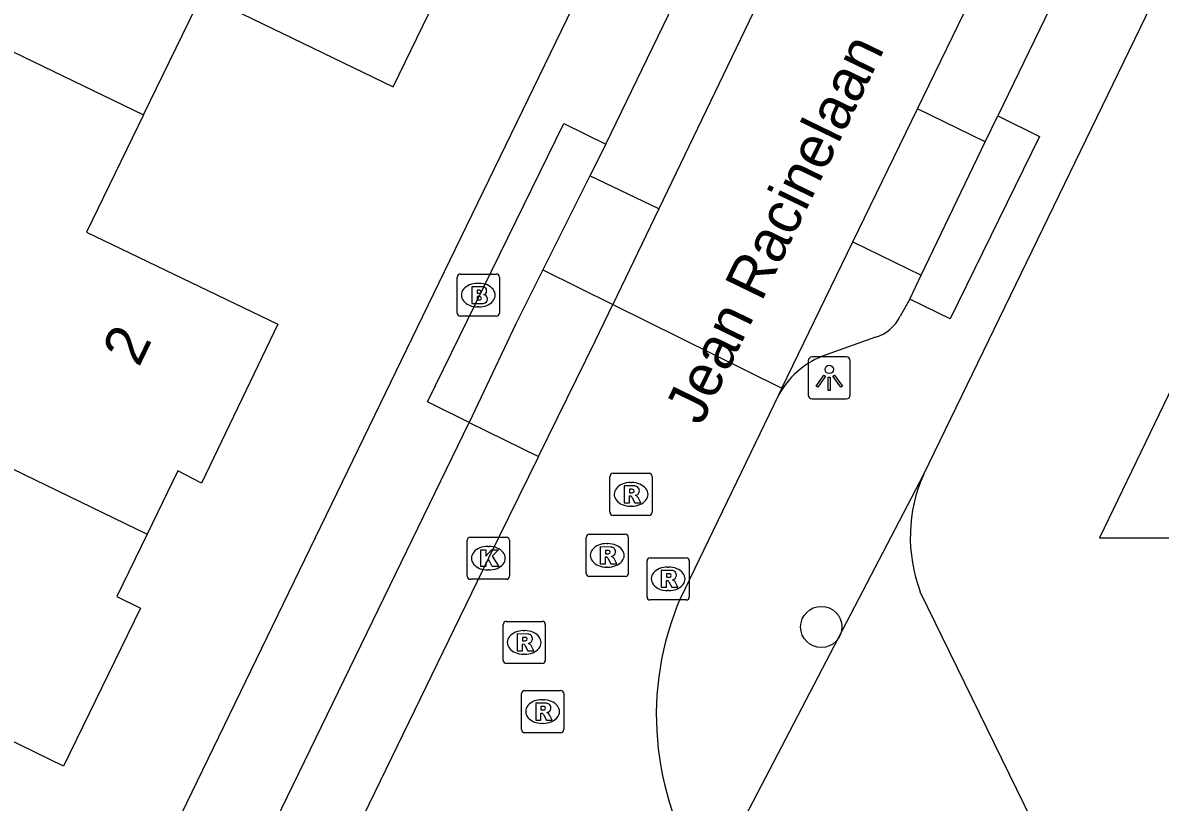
# Model space of a CAD drawing. Extents: x 160457 to 162082, y 388340 to 389736.
# Drawn here: x 160681.02 to 160707.98, y 388938.55 to 388957.02 of the extents above; entities that cross this region are included whole.
import ezdxf

# ---------------------------------------------------------------- set-up
doc = ezdxf.new("R2010")
doc.units = 0
for name, color, linetype in [('IMGEO_Boom', 7, 'Continuous'), ('IMGEO_Brandkraan', 7, 'Continuous'), ('IMGEO_Kolk', 7, 'Continuous'), ('IMGEO_Lichtpunt', 7, 'Continuous'), ('IMGEO_Openbare_ruimte_label', 7, 'Continuous'), ('IMGEO_Pand', 7, 'Continuous'), ('IMGEO_Pand_nummerreeks', 7, 'Continuous'), ('IMGEO_Parkeervlak_open', 7, 'Continuous'), ('IMGEO_Rijbaan_lokaal_gesloten', 7, 'Continuous'), ('IMGEO_Rijbaan_lokaal_open', 7, 'Continuous'), ('IMGEO_Rioolput', 7, 'Continuous'), ('IMGEO_Voetpad_open', 7, 'Continuous')]:
    doc.layers.add(name, color=color, linetype=linetype)

msp = doc.modelspace()

# ---------------------------------------------------------------- linework, layer by layer
at = {"layer": 'IMGEO_Boom'}
msp.add_circle((160699.949, 388942.7), 0.489, dxfattribs=at)
at = {"layer": 'IMGEO_Brandkraan'}
for p, q in [((160691.319, 388950.14), (160691.319, 388950.992)), ((160691.394, 388951.066), (160692.246, 388951.066)), ((160692.32, 388950.992), (160692.32, 388950.14)), ((160691.807, 388950.846), (160691.832, 388950.846)), ((160691.83, 388950.286), (160691.805, 388950.286)), ((160692.246, 388950.066), (160691.394, 388950.066))]:
    msp.add_line(p, q, dxfattribs=at)
for points in [[(160691.319, 388950.14), (160691.319, 388950.992)], [(160691.394, 388951.066), (160692.246, 388951.066)], [(160692.32, 388950.992), (160692.32, 388950.14)], [(160691.667, 388950.766), (160691.667, 388950.366), (160691.88, 388950.366)], [(160691.898, 388950.766), (160691.667, 388950.766)], [(160691.846, 388950.685), (160691.792, 388950.685), (160691.792, 388950.609)], [(160691.792, 388950.609), (160691.845, 388950.609)], [(160691.854, 388950.533), (160691.792, 388950.533), (160691.792, 388950.452)], [(160691.792, 388950.452), (160691.854, 388950.452)], [(160692.246, 388950.066), (160691.394, 388950.066)]]:
    msp.add_lwpolyline(points, dxfattribs=at)
for centre, radius, start, end in [((160691.396, 388950.99), 0.0765, 91.552, 178.448), ((160691.396, 388950.99), 0.0765, 91.552, 178.448), ((160692.244, 388950.99), 0.0765, 1.552, 88.448), ((160692.244, 388950.99), 0.0765, 1.552, 88.448), ((160691.847, 388950.647), 0.0379, 267.8285, 90.9355), ((160691.902, 388950.621), 0.145, 59.4692, 91.5367), ((160691.927, 388950.668), 0.0922, 285.5137, 58.1501), ((160691.855, 388950.492), 0.0404, 269.8759, 90.5077), ((160691.886, 388950.617), 0.251, 268.6676, 293.5347), ((160691.932, 388950.476), 0.105, 301.3115, 78.989), ((160691.396, 388950.142), 0.0765, 181.552, 268.448), ((160691.396, 388950.142), 0.0765, 181.552, 268.448), ((160692.244, 388950.142), 0.0765, 271.552, 358.448), ((160692.244, 388950.142), 0.0765, 271.552, 358.448)]:
    msp.add_arc(centre, radius, start, end, dxfattribs=at)
for centre, major_axis, ratio, start_param, end_param in [((160691.806, 388950.566), (-0.387, 0.002), 0.722429, 4.712389, 7.853982), ((160691.831, 388950.566), (-0.39, 0.002), 0.717154, 1.570796, 4.712389)]:
    msp.add_ellipse(centre, major_axis=major_axis, ratio=ratio, start_param=start_param, end_param=end_param, dxfattribs=at)
at = {"layer": 'IMGEO_Kolk'}
for p, q in [((160691.558, 388943.905), (160691.558, 388944.757)), ((160691.633, 388944.831), (160692.485, 388944.831)), ((160692.559, 388944.757), (160692.559, 388943.905)), ((160692.046, 388944.611), (160692.071, 388944.611)), ((160692.069, 388944.051), (160692.044, 388944.051)), ((160692.485, 388943.831), (160691.633, 388943.831))]:
    msp.add_line(p, q, dxfattribs=at)
for points in [[(160691.558, 388943.905), (160691.558, 388944.757)], [(160691.633, 388944.831), (160692.485, 388944.831)], [(160692.559, 388944.757), (160692.559, 388943.905)], [(160691.879, 388944.531), (160692.002, 388944.531), (160692.002, 388944.38), (160692.132, 388944.531), (160692.296, 388944.531), (160692.15, 388944.38), (160692.303, 388944.131), (160692.151, 388944.131), (160692.066, 388944.295), (160692.002, 388944.228), (160692.002, 388944.131), (160691.879, 388944.131), (160691.879, 388944.531)], [(160692.485, 388943.831), (160691.633, 388943.831)]]:
    msp.add_lwpolyline(points, dxfattribs=at)
for centre, start, end in [((160691.635, 388944.755), 91.552, 178.448), ((160691.635, 388944.755), 91.552, 178.448), ((160692.483, 388944.755), 1.552, 88.448), ((160692.483, 388944.755), 1.552, 88.448), ((160691.635, 388943.907), 181.552, 268.448), ((160691.635, 388943.907), 181.552, 268.448), ((160692.483, 388943.907), 271.552, 358.448), ((160692.483, 388943.907), 271.552, 358.448)]:
    msp.add_arc(centre, 0.0765, start, end, dxfattribs=at)
for centre, major_axis, ratio, start_param, end_param in [((160692.045, 388944.331), (-0.387, 0.002), 0.722429, 4.712389, 7.853982), ((160692.07, 388944.331), (-0.39, 0.002), 0.717154, 1.570796, 4.712389)]:
    msp.add_ellipse(centre, major_axis=major_axis, ratio=ratio, start_param=start_param, end_param=end_param, dxfattribs=at)
at = {"layer": 'IMGEO_Lichtpunt'}
for p, q in [((160700.541, 388949.103), (160699.733, 388949.103)), ((160700.541, 388949.103), (160699.733, 388949.103)), ((160699.639, 388949.008), (160699.639, 388948.201)), ((160699.639, 388949.008), (160699.639, 388948.201)), ((160700.635, 388948.201), (160700.635, 388949.008)), ((160700.635, 388948.201), (160700.635, 388949.008)), ((160699.733, 388948.107), (160700.541, 388948.107)), ((160699.733, 388948.107), (160700.541, 388948.107))]:
    msp.add_line(p, q, dxfattribs=at)
for points in [[(160700.013, 388948.672), (160700.052, 388948.644), (160699.864, 388948.382), (160699.826, 388948.409), (160700.013, 388948.672)], [(160700.115, 388948.624), (160700.162, 388948.624), (160700.162, 388948.302), (160700.115, 388948.302), (160700.115, 388948.624)], [(160700.225, 388948.644), (160700.263, 388948.671), (160700.45, 388948.409), (160700.411, 388948.381), (160700.225, 388948.644)]]:
    msp.add_lwpolyline(points, dxfattribs=at)
msp.add_circle((160700.138, 388948.806), 0.0994, dxfattribs=at)
for centre, start, end in [((160699.733, 388949.008), 90, 180), ((160699.733, 388949.008), 90, 180), ((160700.541, 388949.008), 0, 90), ((160700.541, 388949.008), 0, 90), ((160699.733, 388948.201), 180, 270), ((160699.733, 388948.201), 180, 270), ((160700.541, 388948.201), 270, 0), ((160700.541, 388948.201), 270, 360)]:
    msp.add_arc(centre, 0.0946, start, end, dxfattribs=at)
at = {"layer": 'IMGEO_Pand'}
for points in [[(160683.886, 388954.841), (160685.274, 388957.702), (160689.806, 388955.5), (160691.628, 388959.263), (160691.061, 388959.537), (160691.781, 388961.017)], [(160676.722, 388958.308), (160683.886, 388954.841)], [(160711.423, 388956.71), (160710.697, 388955.213), (160710.13, 388955.488), (160708.309, 388951.732), (160709.588, 388951.115), (160706.546, 388944.81), (160711.543, 388944.812)], [(160683.886, 388954.841), (160682.536, 388952.059), (160687.072, 388949.879), (160685.262, 388946.113), (160684.697, 388946.401), (160683.97, 388944.903)], [(160673.574, 388949.941), (160683.97, 388944.903)], [(160683.97, 388944.903), (160683.25, 388943.421), (160683.816, 388943.144), (160681.987, 388939.4), (160677.378, 388941.651), (160676.02, 388938.842)]]:
    msp.add_lwpolyline(points, dxfattribs=at)
at = {"layer": 'IMGEO_Parkeervlak_open'}
for points in [[(160703.837, 388954.2), (160702.227, 388954.981)], [(160696.1, 388952.612), (160694.467, 388953.396)], [(160700.698, 388951.828), (160702.319, 388951.042)], [(160693.351, 388951.163), (160695.01, 388950.344)], [(160691.606, 388947.55), (160693.247, 388946.742)]]:
    msp.add_lwpolyline(points, dxfattribs=at)
at = {"layer": 'IMGEO_Rijbaan_lokaal_gesloten'}
for points in [[(160702.227, 388954.981), (160703.612, 388957.837), (160707.335, 388965.483)], [(160700.994, 388962.767), (160699.556, 388959.806), (160696.1, 388952.612)], [(160700.698, 388951.828), (160702.227, 388954.981)], [(160696.1, 388952.612), (160695.01, 388950.344)], [(160699.018, 388948.363), (160700.698, 388951.828)]]:
    msp.add_lwpolyline(points, dxfattribs=at)
at = {"layer": 'IMGEO_Rijbaan_lokaal_open'}
for points in [[(160693.247, 388946.742), (160694.6, 388949.491), (160695.01, 388950.344)], [(160695.01, 388950.344), (160699.018, 388948.363)], [(160699.018, 388948.363), (160698.937, 388948.196)], [(160698.937, 388948.196), (160696.612, 388943.387)], [(160693.247, 388946.742), (160692.061, 388944.331), (160688.141, 388936.264)]]:
    msp.add_lwpolyline(points, dxfattribs=at)
msp.add_arc((160703.056, 388940.609), 7.017, 156.675, 212.9012, dxfattribs=at)
at = {"layer": 'IMGEO_Rioolput'}
for p, q in [((160695.016, 388946.344), (160695.868, 388946.344)), ((160694.941, 388945.418), (160694.941, 388946.27)), ((160695.429, 388946.124), (160695.454, 388946.124)), ((160695.942, 388946.27), (160695.942, 388945.418)), ((160695.452, 388945.564), (160695.427, 388945.564)), ((160695.868, 388945.344), (160695.016, 388945.344)), ((160694.375, 388943.971), (160694.375, 388944.823)), ((160694.45, 388944.897), (160695.302, 388944.897)), ((160695.376, 388944.823), (160695.376, 388943.971)), ((160694.863, 388944.677), (160694.888, 388944.677)), ((160695.819, 388943.415), (160695.819, 388944.267)), ((160695.894, 388944.341), (160696.746, 388944.341)), ((160696.82, 388944.267), (160696.82, 388943.415)), ((160695.302, 388943.897), (160694.45, 388943.897)), ((160694.886, 388944.117), (160694.861, 388944.117)), ((160696.307, 388944.121), (160696.332, 388944.121)), ((160696.33, 388943.561), (160696.305, 388943.561)), ((160696.746, 388943.341), (160695.894, 388943.341)), ((160692.482, 388942.834), (160693.334, 388942.834)), ((160692.407, 388941.908), (160692.407, 388942.76)), ((160692.895, 388942.614), (160692.92, 388942.614)), ((160693.408, 388942.76), (160693.408, 388941.908)), ((160692.918, 388942.054), (160692.893, 388942.054)), ((160693.334, 388941.834), (160692.482, 388941.834)), ((160692.918, 388941.195), (160693.77, 388941.195)), ((160692.843, 388940.269), (160692.843, 388941.121)), ((160693.331, 388940.975), (160693.356, 388940.975)), ((160693.844, 388941.121), (160693.844, 388940.269)), ((160693.354, 388940.415), (160693.329, 388940.415)), ((160693.77, 388940.195), (160692.918, 388940.195))]:
    msp.add_line(p, q, dxfattribs=at)
for points in [[(160695.016, 388946.344), (160695.868, 388946.344)], [(160694.941, 388945.418), (160694.941, 388946.27)], [(160695.942, 388946.27), (160695.942, 388945.418)], [(160695.53, 388946.042), (160695.278, 388946.044), (160695.278, 388945.644)], [(160695.278, 388945.644), (160695.402, 388945.644), (160695.402, 388945.806), (160695.413, 388945.806)], [(160695.456, 388945.963), (160695.402, 388945.963), (160695.402, 388945.882)], [(160695.402, 388945.882), (160695.454, 388945.882)], [(160695.46, 388945.777), (160695.531, 388945.644), (160695.671, 388945.644), (160695.606, 388945.77)], [(160695.868, 388945.344), (160695.016, 388945.344)], [(160694.375, 388943.971), (160694.375, 388944.823)], [(160694.45, 388944.897), (160695.302, 388944.897)], [(160695.376, 388944.823), (160695.376, 388943.971)], [(160694.964, 388944.595), (160694.712, 388944.597), (160694.712, 388944.197)], [(160694.89, 388944.516), (160694.836, 388944.516), (160694.836, 388944.435)], [(160694.836, 388944.435), (160694.888, 388944.435)], [(160694.712, 388944.197), (160694.836, 388944.197), (160694.836, 388944.359), (160694.847, 388944.359)], [(160694.894, 388944.33), (160694.965, 388944.197), (160695.105, 388944.197), (160695.04, 388944.323)], [(160695.819, 388943.415), (160695.819, 388944.267)], [(160695.894, 388944.341), (160696.746, 388944.341)], [(160696.82, 388944.267), (160696.82, 388943.415)], [(160695.302, 388943.897), (160694.45, 388943.897)], [(160696.408, 388944.039), (160696.156, 388944.041), (160696.156, 388943.641)], [(160696.334, 388943.96), (160696.28, 388943.96), (160696.28, 388943.879)], [(160696.156, 388943.641), (160696.28, 388943.641), (160696.28, 388943.803), (160696.291, 388943.803)], [(160696.28, 388943.879), (160696.332, 388943.879)], [(160696.338, 388943.774), (160696.409, 388943.641), (160696.549, 388943.641), (160696.484, 388943.767)], [(160696.746, 388943.341), (160695.894, 388943.341)], [(160692.482, 388942.834), (160693.334, 388942.834)], [(160692.407, 388941.908), (160692.407, 388942.76)], [(160693.408, 388942.76), (160693.408, 388941.908)], [(160692.996, 388942.532), (160692.744, 388942.534), (160692.744, 388942.134)], [(160692.744, 388942.134), (160692.868, 388942.134), (160692.868, 388942.296), (160692.879, 388942.296)], [(160692.922, 388942.453), (160692.868, 388942.453), (160692.868, 388942.372)], [(160692.868, 388942.372), (160692.92, 388942.372)], [(160692.926, 388942.267), (160692.997, 388942.134), (160693.137, 388942.134), (160693.072, 388942.26)], [(160693.334, 388941.834), (160692.482, 388941.834)], [(160692.918, 388941.195), (160693.77, 388941.195)], [(160692.843, 388940.269), (160692.843, 388941.121)], [(160693.844, 388941.121), (160693.844, 388940.269)], [(160693.432, 388940.893), (160693.18, 388940.895), (160693.18, 388940.495)], [(160693.18, 388940.495), (160693.304, 388940.495), (160693.304, 388940.657), (160693.315, 388940.657)], [(160693.358, 388940.814), (160693.304, 388940.814), (160693.304, 388940.733)], [(160693.304, 388940.733), (160693.356, 388940.733)], [(160693.362, 388940.628), (160693.433, 388940.495), (160693.573, 388940.495), (160693.508, 388940.621)], [(160693.77, 388940.195), (160692.918, 388940.195)]]:
    msp.add_lwpolyline(points, dxfattribs=at)
for centre, radius, start, end in [((160695.018, 388946.268), 0.0765, 91.552, 178.448), ((160695.018, 388946.268), 0.0765, 91.552, 178.448), ((160695.866, 388946.268), 0.0765, 1.552, 88.448), ((160695.866, 388946.268), 0.0765, 1.552, 88.448), ((160695.412, 388945.753), 0.0533, 26.0293, 88.6989), ((160695.438, 388946.071), 0.19, 274.7715, 282.9687), ((160695.462, 388945.867), 0.0964, 77.0061, 93.1865), ((160695.476, 388945.924), 0.0378, 276.6634, 79.6772), ((160695.529, 388945.932), 0.109, 350.3612, 89.416), ((160695.527, 388945.932), 0.112, 277.5842, 350.9817), ((160695.511, 388945.717), 0.108, 29.5134, 73.7905), ((160695.018, 388945.42), 0.0765, 181.552, 268.448), ((160695.018, 388945.42), 0.0765, 181.552, 268.448), ((160695.866, 388945.42), 0.0765, 271.552, 358.448), ((160695.866, 388945.42), 0.0765, 271.552, 358.448), ((160694.452, 388944.821), 0.0765, 91.552, 178.448), ((160694.452, 388944.821), 0.0765, 91.552, 178.448), ((160695.3, 388944.821), 0.0765, 1.552, 88.448), ((160695.3, 388944.821), 0.0765, 1.552, 88.448), ((160694.872, 388944.624), 0.19, 274.7715, 282.9687), ((160694.896, 388944.42), 0.0964, 77.0061, 93.1865), ((160694.91, 388944.477), 0.0378, 276.6634, 79.6772), ((160694.963, 388944.485), 0.109, 350.3612, 89.416), ((160694.961, 388944.485), 0.112, 277.5842, 350.9817), ((160694.846, 388944.306), 0.0533, 26.0293, 88.6989), ((160694.945, 388944.27), 0.108, 29.5134, 73.7905), ((160695.896, 388944.265), 0.0765, 91.552, 178.448), ((160695.896, 388944.265), 0.0765, 91.552, 178.448), ((160696.744, 388944.265), 0.0765, 1.552, 88.448), ((160696.744, 388944.265), 0.0765, 1.552, 88.448), ((160694.452, 388943.973), 0.0765, 181.552, 268.448), ((160694.452, 388943.973), 0.0765, 181.552, 268.448), ((160695.3, 388943.973), 0.0765, 271.552, 358.448), ((160695.3, 388943.973), 0.0765, 271.552, 358.448), ((160696.34, 388943.864), 0.0964, 77.0061, 93.1865), ((160696.354, 388943.921), 0.0378, 276.6634, 79.6772), ((160696.407, 388943.929), 0.109, 350.3612, 89.416), ((160696.405, 388943.929), 0.112, 277.5842, 350.9817), ((160696.29, 388943.75), 0.0533, 26.0293, 88.6989), ((160696.316, 388944.068), 0.19, 274.7715, 282.9687), ((160696.389, 388943.714), 0.108, 29.5134, 73.7905), ((160695.896, 388943.417), 0.0765, 181.552, 268.448), ((160695.896, 388943.417), 0.0765, 181.552, 268.448), ((160696.744, 388943.417), 0.0765, 271.552, 358.448), ((160696.744, 388943.417), 0.0765, 271.552, 358.448), ((160692.484, 388942.758), 0.0765, 91.552, 178.448), ((160692.484, 388942.758), 0.0765, 91.552, 178.448), ((160693.332, 388942.758), 0.0765, 1.552, 88.448), ((160693.332, 388942.758), 0.0765, 1.552, 88.448), ((160692.878, 388942.243), 0.0533, 26.0293, 88.6989), ((160692.904, 388942.561), 0.19, 274.7715, 282.9687), ((160692.928, 388942.357), 0.0964, 77.0061, 93.1865), ((160692.942, 388942.414), 0.0378, 276.6634, 79.6772), ((160692.995, 388942.422), 0.109, 350.3612, 89.416), ((160692.993, 388942.422), 0.112, 277.5842, 350.9817), ((160692.977, 388942.207), 0.108, 29.5134, 73.7905), ((160692.484, 388941.91), 0.0765, 181.552, 268.448), ((160692.484, 388941.91), 0.0765, 181.552, 268.448), ((160693.332, 388941.91), 0.0765, 271.552, 358.448), ((160693.332, 388941.91), 0.0765, 271.552, 358.448), ((160692.92, 388941.119), 0.0765, 91.552, 178.448), ((160692.92, 388941.119), 0.0765, 91.552, 178.448), ((160693.768, 388941.119), 0.0765, 1.552, 88.448), ((160693.768, 388941.119), 0.0765, 1.552, 88.448), ((160693.314, 388940.604), 0.0533, 26.0293, 88.6989), ((160693.34, 388940.922), 0.19, 274.7715, 282.9687), ((160693.364, 388940.718), 0.0964, 77.0061, 93.1865), ((160693.378, 388940.775), 0.0378, 276.6634, 79.6772), ((160693.431, 388940.783), 0.109, 350.3612, 89.416), ((160693.429, 388940.783), 0.112, 277.5842, 350.9817), ((160693.413, 388940.568), 0.108, 29.5134, 73.7905), ((160692.92, 388940.271), 0.0765, 181.552, 268.448), ((160692.92, 388940.271), 0.0765, 181.552, 268.448), ((160693.768, 388940.271), 0.0765, 271.552, 358.448), ((160693.768, 388940.271), 0.0765, 271.552, 358.448)]:
    msp.add_arc(centre, radius, start, end, dxfattribs=at)
for centre, major_axis, ratio, start_param, end_param in [((160695.428, 388945.844), (-0.387, 0.002), 0.722429, 4.712389, 7.853982), ((160695.453, 388945.844), (-0.39, 0.002), 0.717154, 1.570796, 4.712389), ((160694.862, 388944.397), (-0.387, 0.002), 0.722429, 4.712389, 7.853982), ((160694.887, 388944.397), (-0.39, 0.002), 0.717154, 1.570796, 4.712389), ((160696.306, 388943.841), (-0.387, 0.002), 0.722429, 4.712389, 7.853982), ((160696.331, 388943.841), (-0.39, 0.002), 0.717154, 1.570796, 4.712389), ((160692.894, 388942.334), (-0.387, 0.002), 0.722429, 4.712389, 7.853982), ((160692.919, 388942.334), (-0.39, 0.002), 0.717154, 1.570796, 4.712389), ((160693.33, 388940.695), (-0.387, 0.002), 0.722429, 4.712389, 7.853982), ((160693.355, 388940.695), (-0.39, 0.002), 0.717154, 1.570796, 4.712389)]:
    msp.add_ellipse(centre, major_axis=major_axis, ratio=ratio, start_param=start_param, end_param=end_param, dxfattribs=at)
at = {"layer": 'IMGEO_Voetpad_open'}
for points in [[(160717.954, 389006.662), (160714.723, 389000), (160704.109, 388978.111), (160691.138, 388951.382), (160678.026, 388924.35)], [(160702.377, 388946.323), (160728.414, 389000), (160729.207, 389001.634)], [(160708.596, 388964.04), (160704.131, 388954.813)], [(160694.843, 388954.148), (160699.037, 388962.811)], [(160704.131, 388954.813), (160705.119, 388954.329), (160703.003, 388950.006), (160702.046, 388950.474)], [(160703.837, 388954.2), (160704.131, 388954.813)], [(160691.606, 388947.55), (160690.618, 388948.034), (160693.849, 388954.635), (160694.843, 388954.148)], [(160694.843, 388954.148), (160694.467, 388953.396)], [(160702.319, 388951.042), (160703.837, 388954.2)], [(160694.467, 388953.396), (160693.351, 388951.163)], [(160693.351, 388951.163), (160692.713, 388949.888), (160691.606, 388947.55)], [(160702.046, 388950.474), (160702.319, 388951.042)], [(160702.046, 388950.474), (160701.817, 388950.065)], [(160701.232, 388949.569), (160699.958, 388949.11)], [(160686.63, 388937.298), (160691.606, 388947.55)], [(160697.568, 388937.092), (160702.377, 388946.323)], [(160746.543, 388853.042), (160702.295, 388943.534)]]:
    msp.add_lwpolyline(points, dxfattribs=at)
for centre, radius, start, end in [((160700.965, 388950.476), 0.946, 286.3706, 334.2161), ((160700.72, 388947.232), 2.027, 112.0747, 151.5952), ((160705.734, 388944.829), 3.675, 156.0034, 200.6284)]:
    msp.add_arc(centre, radius, start, end, dxfattribs=at)

# ---------------------------------------------------------------- texts
at = {"layer": 'IMGEO_Openbare_ruimte_label'}
msp.add_text('Jean Racinelaan', height=1, rotation=64.0758, dxfattribs=at).set_placement((160697.102, 388947.448))
at = {"layer": 'IMGEO_Pand_nummerreeks'}
msp.add_text('2', height=1, rotation=64.3303, dxfattribs=at).set_placement((160683.775, 388948.838))

doc.saveas('drawing.dxf')
